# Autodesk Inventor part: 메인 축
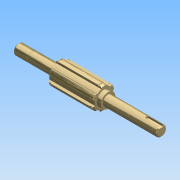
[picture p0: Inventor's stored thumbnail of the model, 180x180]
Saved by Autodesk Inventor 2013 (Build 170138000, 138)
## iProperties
Created: 2015-11
Part Number: 메인 축
Document SubType Name: 모델링
Designer: mdu
Mass: 168.566 g
Surface Area: 72.5104 cm^2
Volume: 21.4461 cm^3
Density: 7.86 g/cm^3
Material: 강철, 연강
변환 표준: STEP AP214IS
파일 이름: C:\Users\SeoGD\Desktop\?쒗뿕\硫붿씤 異?.stp
전처리기: Build: 253, Release: 2010 SP1 - Date: Wed 07/29/2009
전송 단위: 밀리미터
불확실성: 0.01
Author: mdu
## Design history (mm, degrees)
sketch "스케치1"
  geometry: L1 (-69.5, 0)-(69.5, 0); L2 (69.5, 0)-(69.5, 5); L3 (69.5, 5)-(55.5, 5); L4 (55.5, 5)-(55.5, 4.8); L5 (55.5, 4.8)-(54.35, 4.8); L6 (54.35, 4.8)-(54.35, 5); L7 (54.35, 5)-(30.5, 5); L8 (30.5, 5)-(30.5, 9); L9 (30.5, 9)-(-13.5, 9); L10 (-13.5, 9)-(-13.5, 7); L11 (-13.5, 7)-(-17.5, 7); L12 (-17.5, 7)-(-17.5, 5); L13 (-17.5, 5)-(-69.5, 5); L14 (-69.5, 5)-(-69.5, 0); 2 further points
  constraints: 28 end point, 9 parallel, 4 collinear, 2 perpendicular, 1 coincident, 1 horizontal, 1 midpoint
  dimensions: "d2" = 1.15 distance between parallel lines of L6 L4; "d3" = 10 diameter of L3 L1; "d4" = 9.6 diameter of L5 L1; "d6" = 44 distance between parallel lines of L10 L8; "d7" = 4 distance between parallel lines of L12 L10; "d8" = 14 diameter of L11 L1; "d9" = 18 diameter of L9 L1; "d33" = 52 distance from line of L12.end L14; "d37" = 39 distance between parallel lines of L8 L2; "d38" = 14 distance between parallel lines of L2 L4
revolve "회전1" sketch "스케치1" stored, may be unused: angle "d10" = 90 deg
sketch "스케치2"
  geometry: L1 (2.5, 10.712)-(2.5, 8.646); L2 (-2.5, 10.712)-(-2.5, 8.646); A1 r 9 centre (0, 0) between (2.5, 8.646) and (-2.5, 8.646) reference; A2 r 11 centre (0, 0) between (2.5, 10.712) and (-2.5, 10.712); 1 further point
  constraints: 4 end point, 4 point on circle, 2 parallel, 1 centre point, 1 coincident, 1 vertical
  dimensions: "d11" = 22 diameter of A2; "d12" = 5 distance between parallel lines of L1 L2
extrude "돌출1" join sketch "스케치2" stored distance "d13" = 10; taper "d14" = 0 deg
chamfer "모따기1" distance "d15" = 1; stored, may be unused: second distance "d16" = 2, angle "d17" = 45 deg
node "작업 평면1"
node "작업 평면2"
sketch "스케치3"
  geometry: L1 (2.5, 10.712)-(2.5, 10.198); L2 (-2.5, 10.712)-(-2.5, 10.198); A1 r 11 centre (0, 0) between (2.5, 10.712) and (-2.5, 10.712) reference; A2 r 10.5 centre (0, 0) between (2.5, 10.198) and (-2.5, 10.198); 1 further point
  constraints: 4 end point, 2 point on circle, 1 centre point, 1 coincident, 1 parallel, 1 vertical
  dimensions: "d19" = 21 diameter of A2
extrude "돌출2" cut sketch "스케치3" distance "d20" = 1.35; taper "d21" = 0 deg
node "작업 평면3"
sketch "스케치4"
  geometry: L1 (-26, -5)-(-26, 5) reference; L2 (-26, 1.5)-(-12.5, 1.5); L3 (-12.5, -1.5)-(-26, -1.5); A1 r 1.5 centre (-12.5, 0) between (-12.5, -1.5) and (-12.5, 1.5); 2 further points
  constraints: 4 end point, 2 perpendicular, 2 point on circle, 2 point on line, 2 tangent, 1 centre point, 1 horizontal alignment, 1 midpoint
  dimensions: "d25" = 3 distance between parallel lines of L3 L2; "d26" = 15 dimension on A1 L1
extrude "돌출3" cut sketch "스케치4" distance "d27" = 1.8; taper "d28" = 0 deg
chamfer "모따기2" distance "d29" = 1; stored, may be unused: second distance "d30" = 2, angle "d31" = 45 deg
node "솔리드1"
node "솔리드 본체"
node "곡면 본체"
mirror "대칭1"
pattern_circular "원형 패턴1" dims "d23" = 360 deg
node "솔리드2"
other parameters: "d18" = -1.65
